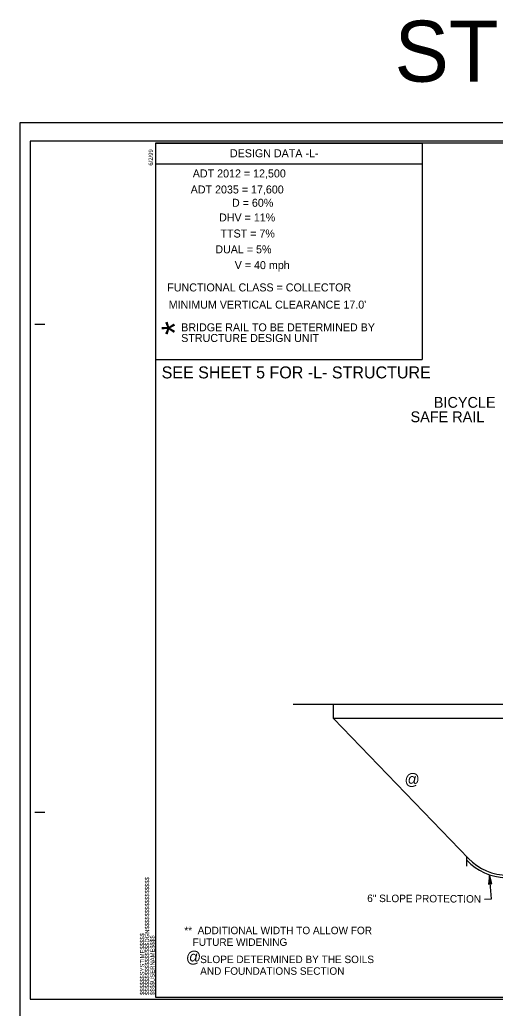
# Model space of a CAD drawing. Extents: x 981824 to 982276, y 44828 to 45204.
# Drawn here: x 981823.9 to 981870.7, y 44916.4 to 45013.7 of the extents above; entities that cross this region are included whole.
import ezdxf

# ---------------------------------------------------------------- set-up
doc = ezdxf.new("R2010")
doc.units = 0
for name, color, linetype in [('Old_Level_1', 7, 'Continuous'), ('Old_Level_11', 7, 'Continuous'), ('Old_Level_18', 7, 'Continuous'), ('Old_Level_3', 7, 'Continuous'), ('Old_Level_40', 7, 'Continuous'), ('Old_Level_41', 7, 'Continuous'), ('Old_Level_50', 7, 'Continuous'), ('Old_Level_51', 7, 'Continuous'), ('Old_Level_52', 7, 'Continuous'), ('Prop Terminator CELL', 7, 'Continuous'), ('Typical Guardrail CELL', 7, 'Continuous'), ('Typical Text Grade Point CELL', 7, 'Continuous')]:
    doc.layers.add(name, color=color, linetype=linetype)

msp = doc.modelspace()

# ---------------------------------------------------------------- linework, layer by layer
at = {"layer": 'Old_Level_1'}
for p, q in [((981939.607, 44946.323), (981850.805, 44946.323)), ((981934.92, 44944.94), (981854.763, 44944.94))]:
    msp.add_line(p, q, dxfattribs=at)
at = {"layer": 'Old_Level_11'}
for p, q in [((981837.237, 45001.552), (981863.484, 45001.552)), ((981837.237, 45001.552), (981837.237, 44980.257)), ((981863.484, 45001.552), (981863.484, 44980.257)), ((981837.237, 44999.528), (981863.484, 44999.528)), ((981837.237, 44980.257), (981863.484, 44980.257)), ((981854.763, 44944.94), (981854.763, 44946.323)), ((981868.068, 44931.177), (981854.763, 44944.94)), ((981867.892, 44930.424), (981867.887, 44931.365))]:
    msp.add_line(p, q, dxfattribs=at)
for radius, end in [(5.58, 267.79074), (5.331, 270)]:
    msp.add_arc((981871.92, 44934.864), radius, 223.74207, end, dxfattribs=at)
at = {"layer": 'Old_Level_18'}
msp.add_line((981837.237, 44917.552), (981837.237, 44917.552), dxfattribs=at)
msp.add_line((981837.237, 44917.552), (981837.237, 44917.552), dxfattribs=at)
msp.add_lwpolyline([(981957.237, 45001.552), (981837.237, 45001.552), (981837.237, 44917.552), (981957.237, 44917.552)], close=True, dxfattribs=at)
at = {"layer": 'Old_Level_40'}
msp.add_line((981837.237, 44917.552), (981837.237, 44917.552), dxfattribs=at)
msp.add_line((981837.237, 44917.552), (981837.237, 44917.552), dxfattribs=at)
msp.add_line((981837.237, 44917.552), (981837.237, 44917.552), dxfattribs=at)
msp.add_line((981837.237, 44917.552), (981837.237, 44917.552), dxfattribs=at)
at = {"layer": 'Old_Level_41'}
for p, q in [((981825.357, 44983.752), (981826.357, 44983.752)), ((981825.357, 44935.752), (981826.357, 44935.752))]:
    msp.add_line(p, q, dxfattribs=at)
msp.add_lwpolyline([(981840.237, 44917.552), (981840.237, 44917.552)], dxfattribs=at)
at = {"layer": 'Old_Level_50'}
msp.add_lwpolyline([(981958.237, 45001.756), (981824.917, 45001.756), (981824.917, 44917.348), (981958.237, 44917.348)], close=True, dxfattribs=at)
at = {"layer": 'Old_Level_51'}
msp.add_lwpolyline([(981958.597, 45003.552), (981823.877, 45003.552), (981823.877, 44915.552), (981958.597, 44915.552)], close=True, dxfattribs=at)
at = {"layer": 'Old_Level_52'}
msp.add_line((981824.917, 44917.348), (981824.917, 44917.348), dxfattribs=at)
at = {"layer": 'Prop Terminator CELL'}
msp.add_lwpolyline([(981870.36, 44928.679), (981870.137, 44929.564), (981870.046, 44928.65), (981870.197, 44928.777)], close=True, dxfattribs=at)
at = {"layer": 'Typical Guardrail CELL'}
msp.add_lwpolyline([(981869.653, 44927.172), (981870.316, 44927.197), (981870.137, 44929.564)], dxfattribs=at)

# ---------------------------------------------------------------- texts
at = {"layer": 'Old_Level_1'}
msp.add_text('STRUC. REC.', height=6, dxfattribs=at).set_placement((981860.776, 45007.594))
at = {"layer": 'Old_Level_11'}
for s, p in [('BICYCLE', (981864.648, 44975.516)), ('SAFE RAIL', (981862.354, 44974.099))]:
    msp.add_text(s, height=1.063, dxfattribs=at).set_placement(p)
msp.add_text('6" SLOPE PROTECTION', height=0.73819, rotation=359.65623, dxfattribs=at).set_placement((981858.087, 44926.898))
at = {"layer": 'Old_Level_3'}
for s, height, rotation, p in [('DESIGN DATA -L-', 0.7874, 360, (981844.574, 45000.158)), ('ADT 2012 = 12,500', 0.7874, 360, (981840.914, 44998.174)), ('ADT 2035 = 17,600', 0.7874, 360, (981840.707, 44996.596)), ('D = 60%', 0.7874, 360, (981844.774, 44995.286)), ('DHV = 11%', 0.7874, 360, (981843.502, 44993.842)), ('TTST = 7%', 0.7874, 360, (981843.644, 44992.265)), ('DUAL = 5%', 0.7874, 360, (981843.133, 44990.709)), ('V = 40 mph', 0.7874, 360, (981845.041, 44989.156)), ('FUNCTIONAL CLASS = COLLECTOR', 0.7874, 360, (981838.401, 44986.961)), ("MINIMUM VERTICAL CLEARANCE 17.0'  ", 0.7874, 360, (981838.546, 44985.269)), ('*', 2.625, 90, (981840.461, 44982.668)), ('BRIDGE RAIL TO BE DETERMINED BY', 0.7874, 360, (981839.775, 44983.037)), ('STRUCTURE DESIGN UNIT', 0.7874, 360, (981839.775, 44981.987)), ('@', 1.107, 360, (981861.764, 44938.434)), ('**  ADDITIONAL WIDTH TO ALLOW FOR ', 0.73819, 360, (981840.077, 44923.732)), ('   FUTURE WIDENING', 0.73819, 360, (981840.077, 44922.584)), ('@', 1.107, 360, (981840.239, 44920.956)), ('SLOPE DETERMINED BY THE SOILS ', 0.73819, 360, (981841.642, 44920.888)), ('AND FOUNDATIONS SECTION', 0.73819, 360, (981841.642, 44919.74))]:
    msp.add_text(s, height=height, rotation=rotation, dxfattribs=at).set_placement(p)
at = {"layer": 'Old_Level_41'}
for s, p in [('6/2/99', (981836.985, 44999.332)), ('$$$$$$$$$$$$$$$$DGN$$$$$$$$$$$$$$$$', (981836.625, 44917.741)), ('$$$$$$SYSTIME$$$$$', (981836.141, 44917.741)), ('$$$$USERNAME$$$$', (981837.151, 44917.742))]:
    msp.add_text(s, height=0.42, rotation=90, dxfattribs=at).set_placement(p)
at = {"layer": 'Typical Text Grade Point CELL'}
msp.add_text('SEE SHEET 5 FOR -L- STRUCTURE', height=1.1811, rotation=360, dxfattribs=at).set_placement((981837.847, 44978.405))

doc.saveas('drawing.dxf')
